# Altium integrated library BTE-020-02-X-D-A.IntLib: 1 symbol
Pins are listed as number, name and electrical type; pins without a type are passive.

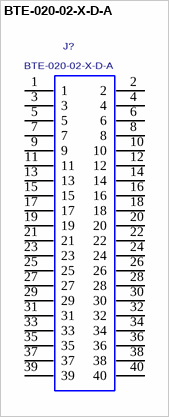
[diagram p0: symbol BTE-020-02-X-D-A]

## BTE-020-02-X-D-A
designator J?
.8mm PITCH DOUBLE ROW TERMINAL ASSEMBLY.; MANUFACTURER: SAMTEC
footprint BTE-020-02-X-D-A
pins: 1, 2, 3, 4, 5, 6, 7, 8, 9, 10, 11, 12, 13, 14, 15, 16, 17, 18, 19, 20, 21, 22, 23, 24, 25, 26, 27, 28, 29, 30, 31, 32, 33, 34, 35, 36, 37, 38, 39, 40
